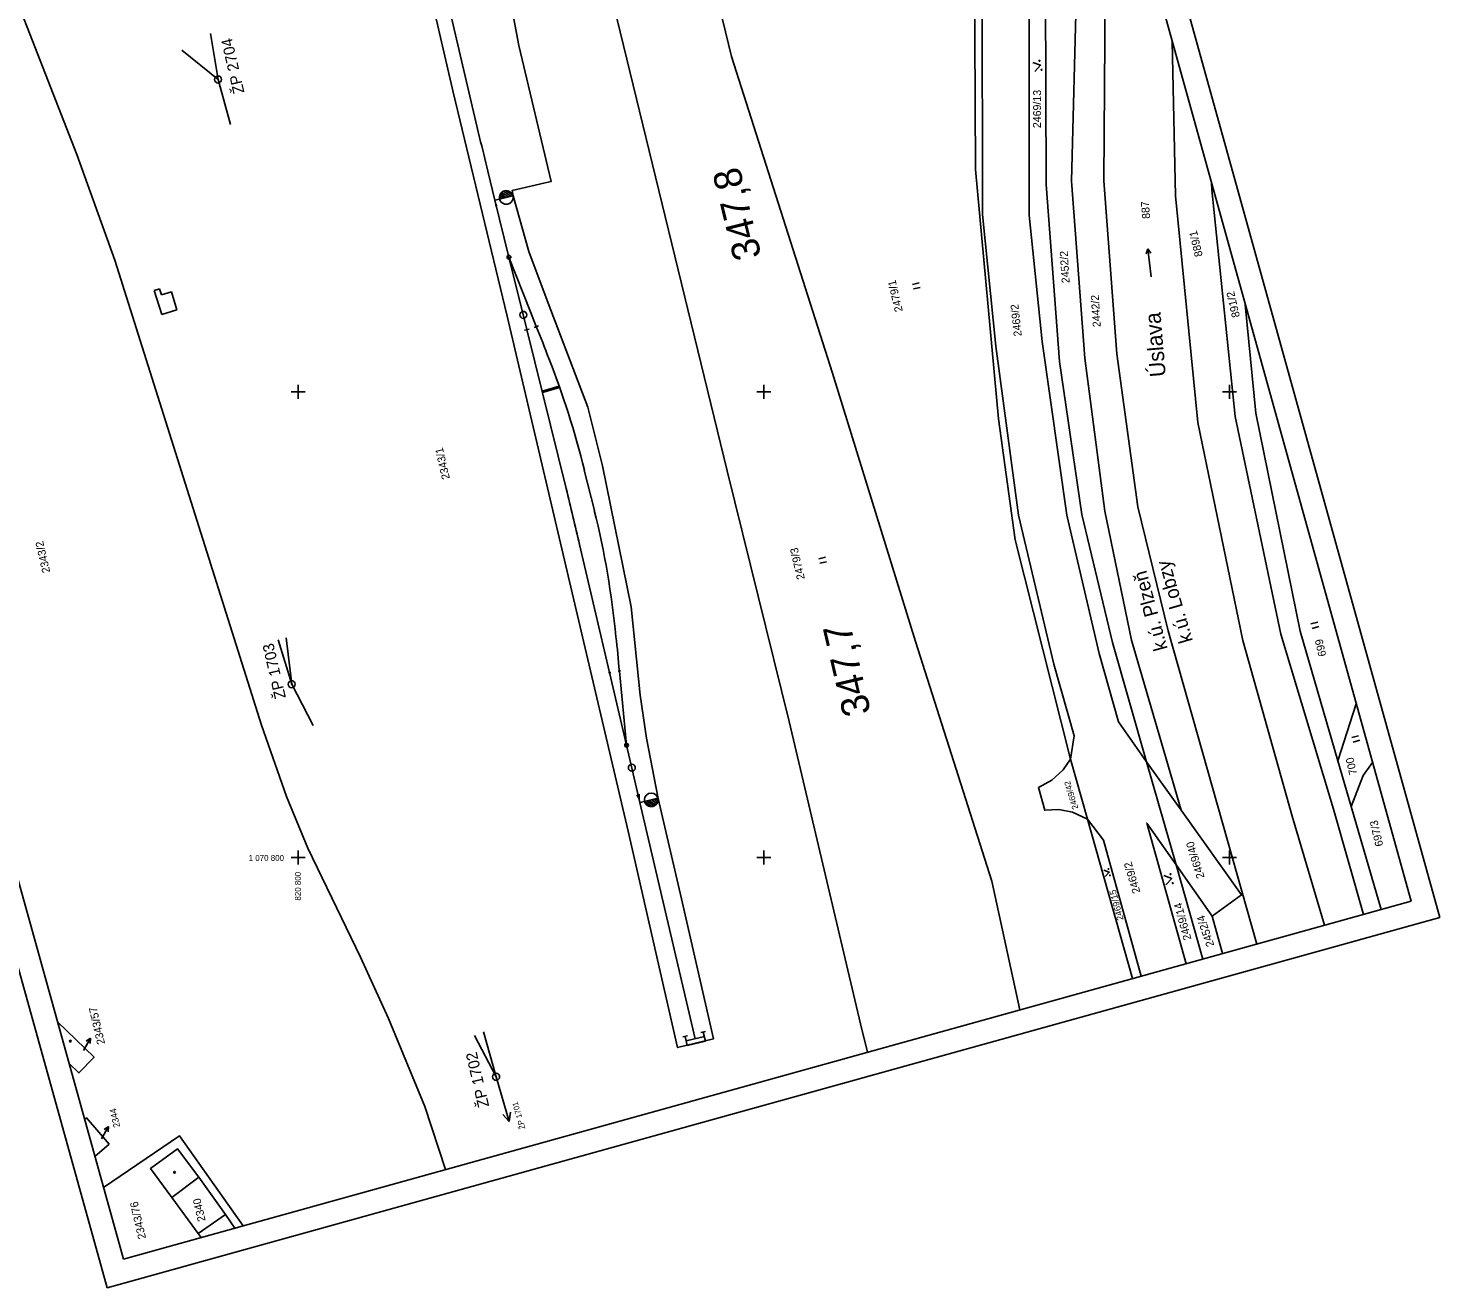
# Model space of a CAD drawing. Extents: x -821122 to -820555, y -1070892 to -1069801.
# Drawn here: x -820857.9 to -820554.8, y -1070892.4 to -1070622 of the extents above; entities that cross this region are included whole.
import ezdxf

# ---------------------------------------------------------------- set-up
doc = ezdxf.new("R2010")
doc.units = 0
for name, color, linetype in [('Hranice drážního pozemku', 7, 'Continuous'), ('Hranice kat_území', 7, 'Continuous'), ('Hranice parcel', 7, 'Continuous'), ('Katastrální hranice', 7, 'Continuous'), ('Osa staničení koleje', 7, 'Continuous'), ('Parcelní čísla', 7, 'Continuous'), ('Pop  PČ popisy', 7, 'Continuous'), ('Ram', 7, 'Continuous'), ('Sttaniceni a namezniky', 7, 'Continuous'), ('Vnitřní kresba', 7, 'Continuous'), ('Vrstva 61', 7, 'Continuous'), ('Vrstva 63', 7, 'Continuous'), ('ZBP', 7, 'Continuous'), ('Značky budov', 7, 'Continuous'), ('Značky kultur', 7, 'Continuous')]:
    doc.layers.add(name, color=color, linetype=linetype)

msp = doc.modelspace()

# ---------------------------------------------------------------- linework, layer by layer
at = {"layer": 'Hranice drážního pozemku'}
for points in [[(-820768.36, -1070867.01), (-820772.76, -1070853.45), (-820780.56, -1070834.55), (-820786.59, -1070821.38), (-820797.89, -1070798.01), (-820802.49, -1070786.9), (-820807.86, -1070771.6), (-820839.34, -1070671.73), (-820847.49, -1070649.05), (-820862.12, -1070611.55), (-820870.18, -1070588.9), (-820893.88, -1070513.71), (-820901.78, -1070488.65), (-820908.48, -1070465.88), (-820912.77, -1070441.75), (-820907.91, -1070440.8), (-820914.43, -1070404.83), (-820920.34, -1070372.85), (-820926.76, -1070341.17), (-820933.59, -1070313.73), (-820939.94, -1070294.5), (-820946.33, -1070279.59), (-820953.63, -1070265.09), (-820959.73, -1070254.91)], [(-820720.44, -1070572.46), (-820743.88, -1070569.76), (-820732.22, -1070617.16), (-820718.37, -1070673.87), (-820707.85, -1070716.96), (-820694.56, -1070770.81), (-820679.24, -1070835.68), (-820677.73, -1070841.82)]]:
    msp.add_lwpolyline(points, dxfattribs=at)
at = {"layer": 'Hranice parcel'}
for p, q in [((-820633.34, -1070773.88), (-820634.1, -1070778.9)), ((-820634.1, -1070778.9), (-820630.5, -1070791.8)), ((-820617.78, -1070779.43), (-820611.45, -1070801.61)), ((-820617.78, -1070779.43), (-820610.37, -1070789.85)), ((-820576.69, -1070779.22), (-820573.83, -1070789.03)), ((-820630.5, -1070791.8), (-820627.05, -1070796.31)), ((-820611.45, -1070801.61), (-820603.74, -1070812.61)), ((-820611.45, -1070801.61), (-820605.69, -1070821.81))]:
    msp.add_line(p, q, dxfattribs=at)
for points in [[(-820768.36, -1070867.01), (-820772.76, -1070853.45), (-820780.56, -1070834.55), (-820786.59, -1070821.38), (-820797.89, -1070798.01), (-820802.49, -1070786.9), (-820807.86, -1070771.6), (-820839.34, -1070671.73), (-820847.49, -1070649.05), (-820862.12, -1070611.55), (-820870.18, -1070588.9), (-820893.88, -1070513.71), (-820901.78, -1070488.65), (-820908.48, -1070465.88), (-820912.77, -1070441.75), (-820907.91, -1070440.8), (-820914.43, -1070404.83), (-820920.34, -1070372.85), (-820926.76, -1070341.17), (-820933.59, -1070313.73), (-820939.94, -1070294.5), (-820946.33, -1070279.59), (-820953.63, -1070265.09), (-820959.73, -1070254.91)], [(-820720.44, -1070572.46), (-820743.88, -1070569.76), (-820732.22, -1070617.16), (-820718.37, -1070673.87), (-820707.85, -1070716.96), (-820694.56, -1070770.81), (-820679.24, -1070835.68), (-820677.73, -1070841.82)], [(-820644.99, -1070832.73), (-820651.05, -1070805.08), (-820667.4, -1070753.6), (-820685.24, -1070696.04), (-820706.9, -1070628.02), (-820713.28, -1070601.74), (-820720.44, -1070572.46)], [(-820653.29, -1070574.2), (-820654.8, -1070594.7), (-820654.5, -1070652.3), (-820649.6, -1070705.8), (-820646, -1070731.8), (-820634.1, -1070778.9)], [(-820649.79, -1070575.18), (-820653.1, -1070612.1), (-820653, -1070661.95), (-820650.17, -1070690.23), (-820645.27, -1070726.49), (-820637.71, -1070758.5), (-820633.34, -1070773.88)], [(-820617.78, -1070779.43), (-820623.84, -1070770.91), (-820627.97, -1070756.18), (-820634.95, -1070726.51), (-820640.2, -1070689.19), (-820643, -1070662.1), (-820643, -1070612.5), (-820639.94, -1070578.04)], [(-820610.37, -1070789.85), (-820621.01, -1070753.33), (-820626.77, -1070725.67), (-820631.06, -1070692.78), (-820633.95, -1070654.83), (-820632.82, -1070613.38), (-820630.65, -1070575.77)], [(-820639.52, -1070614.28), (-820639.34, -1070655.55), (-820636.46, -1070693.5), (-820631.68, -1070726.33), (-820625.08, -1070753.87), (-820617.78, -1070779.43)], [(-820579.57, -1070814.55), (-820586.56, -1070791.11), (-820597.14, -1070753.41), (-820606.77, -1070706.64), (-820611.55, -1070657.93), (-820612.27, -1070624.81)], [(-820571.22, -1070812.23), (-820577.63, -1070789.65), (-820588.95, -1070752.08), (-820598.78, -1070705.34), (-820603.8, -1070656.67), (-820603.83, -1070655.2)], [(-820596.59, -1070681.25), (-820594.3, -1070704.61), (-820584.78, -1070751.4), (-820576.69, -1070779.22)], [(-820576.69, -1070779.22), (-820572.76, -1070767.02)], [(-820634.1, -1070778.9), (-820635.67, -1070781.21), (-820638.11, -1070783.39)], [(-820569.26, -1070779.62), (-820571.29, -1070782.43), (-820573.83, -1070789.03)], [(-820638.11, -1070783.39), (-820641.03, -1070784.97), (-820639.65, -1070789.87), (-820636.63, -1070789.7)], [(-820636.63, -1070789.7), (-820633.7, -1070790.28), (-820630.5, -1070791.8)], [(-820603.74, -1070812.61), (-820597.44, -1070808.04), (-820610.37, -1070789.85)], [(-820573.83, -1070789.03), (-820567.42, -1070811.17)], [(-820630.5, -1070791.8), (-820620.78, -1070826)], [(-820609.26, -1070822.8), (-820617.76, -1070792.61), (-820611.45, -1070801.61)], [(-820627.05, -1070796.31), (-820618.96, -1070825.49)], [(-820603.74, -1070812.61), (-820601.47, -1070820.63)], [(-820851.66, -1070835.29), (-820843.79, -1070842.89), (-820847.05, -1070846.25), (-820849.19, -1070844.2)], [(-820845.84, -1070856.23), (-820845.46, -1070855.9), (-820840.58, -1070861.56)], [(-820841.78, -1070870.88), (-820825.47, -1070859.75), (-820811.78, -1070879.07)], [(-820840.58, -1070861.56), (-820843.63, -1070864.19)], [(-820813.57, -1070879.57), (-820815.61, -1070876.67), (-820821.34, -1070868.62), (-820825.9, -1070862.55), (-820831.68, -1070866.78), (-820827.12, -1070872.98), (-820821.43, -1070880.72), (-820820.83, -1070881.59)]]:
    msp.add_lwpolyline(points, dxfattribs=at)
at = {"layer": 'Katastrální hranice'}
msp.add_lwpolyline([(-820594.11, -1070818.59), (-820613.15, -1070751.36), (-820619.68, -1070724.73), (-820624.16, -1070691.86), (-820626.98, -1070654.7), (-820626.67, -1070614.41), (-820623.69, -1070583.73)], dxfattribs=at)
at = {"layer": 'Osa staničení koleje'}
for p, q in [((-820757.73, -1070658.89), (-820759.28, -1070652.66)), ((-820756.54, -1070657.51), (-820755.28, -1070658.28)), ((-820756.3, -1070657.22), (-820754.75, -1070658.15)), ((-820755.96, -1070656.98), (-820754.23, -1070658.02)), ((-820755.46, -1070656.83), (-820753.95, -1070657.75)), ((-820756.73, -1070658.64), (-820757.73, -1070658.89)), ((-820756.77, -1070658.27), (-820756.32, -1070658.54)), ((-820756.73, -1070658.64), (-820753.88, -1070657.94)), ((-820756.7, -1070657.86), (-820755.8, -1070658.41)), ((-820751.35, -1070686.79), (-820750.38, -1070686.55)), ((-820742.44, -1070720.8), (-820750.87, -1070686.67)), ((-820749.31, -1070686.21), (-820748.38, -1070685.85)), ((-820747.6, -1070699.9), (-820743.94, -1070698.81)), ((-820747.53, -1070700.19), (-820743.84, -1070699.09)), ((-820736.38, -1070725.49), (-820738.53, -1070716.82)), ((-820733.1, -1070760.32), (-820739.54, -1070732.83)), ((-820733.35, -1070760.38), (-820732.86, -1070760.27)), ((-820731.26, -1070760), (-820730.76, -1070759.96)), ((-820729.46, -1070775.91), (-820731.01, -1070759.98)), ((-820722.73, -1070787.29), (-820725.58, -1070787.96)), ((-820725.17, -1070787.86), (-820723.47, -1070788.91)), ((-820724.65, -1070787.74), (-820723.14, -1070788.67)), ((-820724.13, -1070787.62), (-820722.91, -1070788.38)), ((-820723.62, -1070787.5), (-820722.76, -1070788.03)), ((-820723.1, -1070787.38), (-820722.7, -1070787.63)), ((-820725.58, -1070787.96), (-820726.58, -1070788.19)), ((-820714.71, -1070838.92), (-820726.58, -1070788.19)), ((-820725.55, -1070788.06), (-820723.94, -1070789.06)), ((-820716.4, -1070838.28), (-820717.37, -1070838.51)), ((-820712.76, -1070838.46), (-820716.66, -1070839.37)), ((-820712.51, -1070837.37), (-820713.48, -1070837.6))]:
    msp.add_line(p, q, dxfattribs=at)
for points in [[(-820761.02, -1070645.41), (-820786.89, -1070534.87), (-820787.46, -1070532.43), (-820788.03, -1070530), (-820808.6, -1070442.09), (-820809.13, -1070439.8), (-820809.67, -1070437.51), (-820820.71, -1070390.32)], [(-820750.87, -1070686.67), (-820754.71, -1070671.13), (-820757.73, -1070658.89)], [(-820757.3, -1070660.1), (-820757.54, -1070659.67), (-820757.55, -1070660.17)], [(-820748.85, -1070686.03), (-820750.09, -1070682.87), (-820754.71, -1070671.13)], [(-820726.58, -1070788.19), (-820729.46, -1070775.91), (-820733.1, -1070760.32)], [(-820727.24, -1070786.53), (-820726.77, -1070787.41), (-820726.73, -1070786.41)], [(-820716.89, -1070838.4), (-820716.43, -1070840.34), (-820712.54, -1070839.43), (-820712.99, -1070837.49)]]:
    msp.add_lwpolyline(points, dxfattribs=at)
for centre, radius in [((-820754.71, -1070671.13), 0.4), ((-820729.46, -1070775.91), 0.4), ((-820724.16, -1070787.62), 1.46)]:
    msp.add_circle(centre, radius, dxfattribs=at)
for centre, start, end in [((-820755.31, -1070658.29), 13.8982, 193.8591), ((-820755.3, -1070658.3), 193.6439, 14.1134), ((-820724.16, -1070787.62), 193.1913, 13.1522)]:
    msp.add_arc(centre, 1.46, start, end, dxfattribs=at)
for centre, major_axis, ratio, start_param, end_param in [((-821297.45, -1070778.88), (-137, 584.15), 0.921302, 4.712391, 4.724811), ((-820924.28, -1070758.98), (55, 181.87), 0.999992, 5.361609, 5.400139), ((-820922.85, -1070762.38), (-45.59, 184.45), 0.999308, 4.712395, 4.844949), ((-821629.82, -1070941.66), (-228.37, 973.58), 0.914441, 4.712392, 4.724766), ((-820920.82, -1070771.08), (3.93, 189.96), 0.999915, 4.830454, 4.97538), ((-820920.38, -1070774.75), (1, 190), 0.999687, 4.795486, 4.834494)]:
    msp.add_ellipse(centre, major_axis=major_axis, ratio=ratio, start_param=start_param, end_param=end_param, dxfattribs=at)
at = {"layer": 'Parcelní čísla'}
for p, q in [((-820846.05, -1070841.43), (-820844.57, -1070838.82)), ((-820844.57, -1070838.82), (-820845.5, -1070839.45)), ((-820844.57, -1070838.82), (-820844.63, -1070839.94)), ((-820842.22, -1070860.4), (-820840.74, -1070857.79)), ((-820840.74, -1070857.79), (-820841.67, -1070858.42)), ((-820840.74, -1070857.79), (-820840.8, -1070858.91))]:
    msp.add_line(p, q, dxfattribs=at)
at = {"layer": 'Ram'}
msp.add_line((-820560.99, -1070809.39), (-820837.51, -1070886.22), dxfattribs=at)
for points in [[(-820835.94, -1069801.19), (-820554.83, -1070812.86)], [(-820837.51, -1070886.22), (-821115.94, -1069884.19), (-820839.42, -1069807.35)], [(-820839.42, -1069807.35), (-820560.99, -1070809.39)], [(-820840.99, -1070892.38), (-821122.1, -1069880.71)], [(-820554.83, -1070812.86), (-820840.99, -1070892.38)]]:
    msp.add_lwpolyline(points, dxfattribs=at)
at = {"layer": 'Sttaniceni a namezniky'}
for centre in [(-820751.65, -1070683.5), (-820728.33, -1070780.74)]:
    msp.add_circle(centre, 0.75, dxfattribs=at)
at = {"layer": 'Vnitřní kresba'}
for p, q in [((-820830.9, -1070678.29), (-820829.73, -1070677.93)), ((-820829.28, -1070683.43), (-820830.9, -1070678.29)), ((-820829.73, -1070677.93), (-820829.33, -1070679.21)), ((-820829.33, -1070679.21), (-820827.2, -1070678.55)), ((-820827.2, -1070678.55), (-820826.01, -1070682.4)), ((-820826.01, -1070682.4), (-820829.28, -1070683.43)), ((-820827.12, -1070872.98), (-820821.34, -1070868.62)), ((-820821.43, -1070880.72), (-820815.61, -1070876.67))]:
    msp.add_line(p, q, dxfattribs=at)
at = {"layer": 'Vrstva 61'}
for p, q in [((-820800, -1070698.5), (-820800, -1070701.5)), ((-820700, -1070698.5), (-820700, -1070701.5)), ((-820600, -1070698.5), (-820600, -1070701.5)), ((-820801.5, -1070700), (-820798.5, -1070700)), ((-820701.5, -1070700), (-820698.5, -1070700)), ((-820601.5, -1070700), (-820598.5, -1070700)), ((-820800, -1070798.5), (-820800, -1070801.5)), ((-820700, -1070798.5), (-820700, -1070801.5)), ((-820600, -1070798.5), (-820600, -1070801.5)), ((-820801.5, -1070800), (-820798.5, -1070800)), ((-820701.5, -1070800), (-820698.5, -1070800)), ((-820601.5, -1070800), (-820598.5, -1070800))]:
    msp.add_line(p, q, dxfattribs=at)
at = {"layer": 'Vrstva 63'}
msp.add_lwpolyline([(-820756.59, -1070604.3), (-820752.56, -1070625.64), (-820745.66, -1070654.88), (-820746.96, -1070655.19), (-820749.11, -1070655.68), (-820754.03, -1070656.83), (-820753.84, -1070657.98), (-820750.47, -1070669.89), (-820746.26, -1070680.97), (-820737.78, -1070703.32), (-820734.63, -1070715.91), (-820728.44, -1070746.18), (-820726.51, -1070765.13), (-820725.16, -1070774.41), (-820722.68, -1070787.32), (-820717.67, -1070808.86), (-820710.81, -1070838.96), (-820718.49, -1070840.82), (-820729.1, -1070794.38), (-820755.08, -1070683.79), (-820766.7, -1070635.67), (-820782.06, -1070569.19)], dxfattribs=at)
at = {"layer": 'ZBP'}
for p, q in [((-820817.18, -1070632.97), (-820818.82, -1070623.11)), ((-820817.18, -1070632.97), (-820824.95, -1070626.68)), ((-820817.16, -1070633.02), (-820817.19, -1070632.92)), ((-820817.18, -1070632.97), (-820814.49, -1070642.6)), ((-820801.37, -1070762.8), (-820804.31, -1070753.24)), ((-820801.37, -1070762.8), (-820802.58, -1070752.87)), ((-820801.36, -1070762.85), (-820801.38, -1070762.75)), ((-820801.37, -1070762.8), (-820796.75, -1070771.67)), ((-820757.47, -1070847.08), (-820762.09, -1070838.21)), ((-820757.47, -1070847.08), (-820760.16, -1070837.44)), ((-820757.46, -1070847.12), (-820757.48, -1070847.03)), ((-820757.47, -1070847.08), (-820754.7, -1070856.68)), ((-820754.7, -1070856.68), (-820756.02, -1070855.18)), ((-820754.7, -1070856.68), (-820754.38, -1070854.71))]:
    msp.add_line(p, q, dxfattribs=at)
for centre in [(-820817.18, -1070632.97), (-820801.37, -1070762.8), (-820757.47, -1070847.08)]:
    msp.add_circle(centre, 0.756, dxfattribs=at)
at = {"layer": 'Značky budov'}
for centre in [(-820848.91, -1070839.43), (-820826.53, -1070867.59)]:
    msp.add_circle(centre, 0.175, dxfattribs=at)
at = {"layer": 'Značky kultur'}
for p, q in [((-820617.52, -1070669.35), (-820617.91, -1070670.38)), ((-820616.84, -1070675.32), (-820617.52, -1070669.35)), ((-820617.52, -1070669.35), (-820616.91, -1070670.27)), ((-820666.61, -1070676.62), (-820668.07, -1070676.96)), ((-820666.39, -1070677.6), (-820667.85, -1070677.94)), ((-820686.72, -1070735.52), (-820688.18, -1070735.86)), ((-820686.5, -1070736.5), (-820687.96, -1070736.84)), ((-820582.5, -1070749.86), (-820581.05, -1070749.47)), ((-820582.24, -1070750.82), (-820580.79, -1070750.43)), ((-820573.7, -1070774.25), (-820572.26, -1070773.86)), ((-820573.44, -1070775.22), (-820571.99, -1070774.82))]:
    msp.add_line(p, q, dxfattribs=at)
for points in [[(-820641.79, -1070631.23), (-820640.56, -1070629.91), (-820642.25, -1070629.29)], [(-820626.68, -1070804.08), (-820625.81, -1070803.16), (-820626.99, -1070802.71)], [(-820613.64, -1070805.85), (-820612.4, -1070804.53), (-820614.09, -1070803.9)]]:
    msp.add_lwpolyline(points, dxfattribs=at)
for centre, radius in [((-820640.79, -1070628.94), 0.1), ((-820640.33, -1070630.88), 0.1), ((-820625.97, -1070802.48), 0.07), ((-820625.65, -1070803.84), 0.07), ((-820612.63, -1070803.56), 0.1), ((-820612.18, -1070805.51), 0.1)]:
    msp.add_circle(centre, radius, dxfattribs=at)

# ---------------------------------------------------------------- texts
at = {"layer": 'Hranice kat_území'}
for s, rotation, p in [('k.ú. Plzeň', 105.2526, (-820613.24, -1070755.18)), ('k.ú. Lobzy', 106.2332, (-820607.82, -1070753.49))]:
    msp.add_text(s, height=3, rotation=rotation, dxfattribs=at).set_placement(p)
at = {"layer": 'Parcelní čísla'}
for s, height, rotation, p in [('2469/13', 1.7, 89.8008, (-820640.48, -1070643.42)), ('887', 1.7, 95.1041, (-820617, -1070662.81)), ('889/1', 1.7, 103, (-820605.73, -1070670.82)), ('2452/2', 1.7, 93.6922, (-820634.3, -1070676.65)), ('2479/1', 1.7, 103, (-820670.14, -1070682.67)), ('891/2', 1.7, 103, (-820597.74, -1070683.87)), ('2469/2', 1.7, 96.1859, (-820644.59, -1070688.03)), ('2442/2', 1.7, 93.7245, (-820627.63, -1070686.08)), ('2343/1', 1.7, 103, (-820767.38, -1070718.64)), ('2343/2', 1.7, 103, (-820853.21, -1070738.71)), ('2479/3', 1.7, 103, (-820691.16, -1070740.14)), ('699', 1.7, 103, (-820579.18, -1070756.65)), ('700', 1.7, 103, (-820572.56, -1070782.07)), ('2469/42', 1.3, 106.9881, (-820632.43, -1070789.45)), ('697/3', 1.7, 103, (-820566.95, -1070797.42)), ('2469/40', 1.7, 107.3091, (-820605.31, -1070804.24)), ('2469/2', 1.7, 106.4362, (-820619.1, -1070807.44)), ('2469/15', 1.4, 104.8276, (-820622.72, -1070813.33)), ('2469/14', 1.7, 105.209, (-820608.15, -1070817.51)), ('2452/4', 1.7, 108.7311, (-820603.23, -1070818.84)), ('2343/57', 1.7, 103, (-820841.44, -1070839.96)), ('2344', 1.4, 103, (-820838.2, -1070857.81)), ('2343/76', 1.7, 103, (-820832.63, -1070881.73)), ('2340', 1.7, 103, (-820819.84, -1070877.97))]:
    msp.add_text(s, height=height, rotation=rotation, dxfattribs=at).set_placement(p)
at = {"layer": 'Pop  PČ popisy'}
msp.add_text('Úslava', height=3.4, rotation=94.8467, dxfattribs=at).set_placement((-820613.65, -1070696.7))
at = {"layer": 'Sttaniceni a namezniky'}
for s, rotation, p in [('347,8', 103.8826, (-820700.45, -1070670.91)), ('347,7', 103.1734, (-820676.95, -1070768.87))]:
    msp.add_text(s, height=6, rotation=rotation, dxfattribs=at).set_placement(p)
at = {"layer": 'Vrstva 61'}
msp.add_text('1 070 800', height=1.275, dxfattribs=at).set_placement((-820810.61, -1070800.74))
msp.add_text('820 800', height=1.275, rotation=90, dxfattribs=at).set_placement((-820799.4, -1070809.25))
at = {"layer": 'ZBP'}
for s, height, rotation, p in [('ŽP 2704', 2.4, 103, (-820811.5, -1070635.74)), ('ŽP 1703', 2.4, 103, (-820802.6, -1070765.66)), ('ŽP 1702', 2.4, 103, (-820758.95, -1070853.38)), ('ŽP 1701', 1.2, 106.2751, (-820751.19, -1070858.17))]:
    msp.add_text(s, height=height, rotation=rotation, dxfattribs=at).set_placement(p)

doc.saveas('drawing.dxf')
